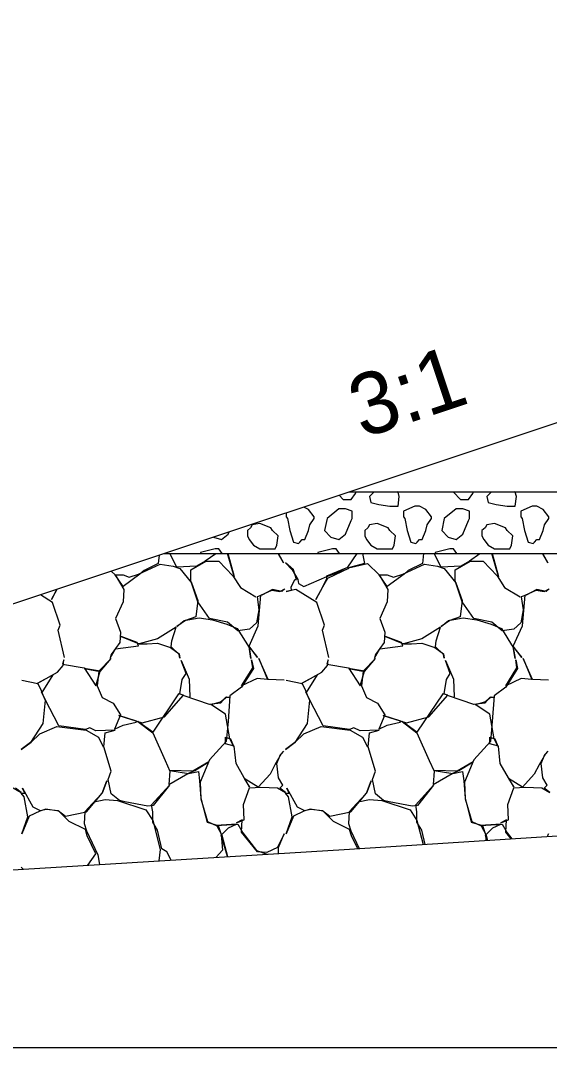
# Model space of a CAD drawing. Extents: x -26 to 4781, y -31 to 24738.
# Drawn here: x 2243.62 to 2252.18, y 8500 to 8516.63 of the extents above; entities that cross this region are included whole.
import ezdxf

# ---------------------------------------------------------------- set-up
doc = ezdxf.new("R2010")
doc.units = 0
for name, color, linetype in [('DESIGN - SHEET - Light Grid', 7, 'Continuous'), ('DESIGN - TRANSPORTATION - Proposed Layout Patterning', 7, 'Continuous'), ('DESIGN - TYPICAL - Finished Grade and Subgrade', 7, 'Continuous'), ('DESIGN - TYPICAL - Finished Grade Slopes Text', 7, 'Continuous'), ('GEOTECHNICAL – SCRATCH – Level 1', 7, 'Continuous'), ('SURVEY - GROUND - Top of Ground', 7, 'Continuous')]:
    doc.layers.add(name, color=color, linetype=linetype)

msp = doc.modelspace()

# ---------------------------------------------------------------- linework, layer by layer
at = {"layer": 'DESIGN - SHEET - Light Grid'}
msp.add_line((2000, 8500), (2300, 8500), dxfattribs=at)
at = {"layer": 'DESIGN - TRANSPORTATION - Proposed Layout Patterning'}
for p, q in [((2249.732, 8508.996), (2249.72, 8509)), ((2251.632, 8508.996), (2251.62, 8509)), ((2247.922, 8508.659), (2247.922, 8508.596)), ((2248.772, 8508.726), (2248.582, 8508.566)), ((2250.672, 8508.726), (2250.482, 8508.566)), ((2247.922, 8508.596), (2247.942, 8508.566)), ((2249.822, 8508.596), (2249.842, 8508.566)), ((2251.722, 8508.596), (2251.742, 8508.566))]:
    msp.add_line(p, q, dxfattribs=at)
for points in [[(2248.779, 8508.945), (2248.842, 8508.876), (2248.972, 8508.876), (2249.042, 8508.976), (2249.054, 8509)], [(2249.348, 8509), (2249.342, 8508.996), (2249.272, 8508.926), (2249.292, 8508.826), (2249.422, 8508.796), (2249.602, 8508.766), (2249.732, 8508.766), (2249.752, 8508.926), (2249.732, 8508.996)], [(2250.633, 8509), (2250.632, 8508.996), (2250.742, 8508.876), (2250.872, 8508.876), (2250.942, 8508.976), (2250.954, 8509)], [(2251.248, 8509), (2251.242, 8508.996), (2251.172, 8508.926), (2251.192, 8508.826), (2251.322, 8508.796), (2251.502, 8508.766), (2251.632, 8508.766), (2251.652, 8508.926), (2251.632, 8508.996)], [(2250.082, 8508.766), (2250.022, 8508.766), (2250.002, 8508.766), (2249.822, 8508.686), (2249.822, 8508.596)], [(2250.272, 8508.566), (2250.272, 8508.596), (2250.182, 8508.716), (2250.082, 8508.766)], [(2251.982, 8508.766), (2251.922, 8508.766), (2251.902, 8508.766), (2251.722, 8508.686), (2251.722, 8508.596)], [(2252.172, 8508.566), (2252.172, 8508.596), (2252.082, 8508.716), (2251.982, 8508.766)], [(2248.372, 8508.566), (2248.372, 8508.596), (2248.282, 8508.716), (2248.207, 8508.754)], [(2248.992, 8508.566), (2248.992, 8508.686), (2248.882, 8508.726), (2248.772, 8508.726)], [(2250.892, 8508.566), (2250.892, 8508.686), (2250.782, 8508.726), (2250.672, 8508.726)], [(2247.672, 8508.416), (2247.492, 8508.486), (2247.372, 8508.466), (2247.342, 8508.416), (2247.292, 8508.376), (2247.292, 8508.286), (2247.322, 8508.226), (2247.392, 8508.136), (2247.492, 8508.076), (2247.622, 8508.076), (2247.742, 8508.076), (2247.772, 8508.136), (2247.792, 8508.286), (2247.702, 8508.376), (2247.672, 8508.416)], [(2247.942, 8508.566), (2247.982, 8508.376), (2248.042, 8508.186), (2248.122, 8508.166), (2248.142, 8508.186), (2248.182, 8508.226)], [(2248.182, 8508.226), (2248.222, 8508.226), (2248.282, 8508.376), (2248.302, 8508.466), (2248.372, 8508.566)], [(2248.582, 8508.566), (2248.542, 8508.376), (2248.642, 8508.266), (2248.772, 8508.226), (2248.882, 8508.316), (2248.972, 8508.536), (2248.992, 8508.566)], [(2249.572, 8508.416), (2249.392, 8508.486), (2249.272, 8508.466), (2249.242, 8508.416), (2249.192, 8508.376), (2249.192, 8508.286), (2249.222, 8508.226), (2249.292, 8508.136), (2249.392, 8508.076), (2249.522, 8508.076), (2249.642, 8508.076), (2249.672, 8508.136), (2249.692, 8508.286), (2249.602, 8508.376), (2249.572, 8508.416)], [(2249.842, 8508.566), (2249.882, 8508.376), (2249.942, 8508.186), (2250.022, 8508.166), (2250.042, 8508.186), (2250.082, 8508.226)], [(2250.082, 8508.226), (2250.122, 8508.226), (2250.182, 8508.376), (2250.202, 8508.466), (2250.272, 8508.566)], [(2250.482, 8508.566), (2250.442, 8508.376), (2250.542, 8508.266), (2250.672, 8508.226), (2250.782, 8508.316), (2250.872, 8508.536), (2250.892, 8508.566)], [(2251.472, 8508.416), (2251.292, 8508.486), (2251.172, 8508.466), (2251.142, 8508.416), (2251.092, 8508.376), (2251.092, 8508.286), (2251.122, 8508.226), (2251.192, 8508.136), (2251.292, 8508.076), (2251.422, 8508.076), (2251.542, 8508.076), (2251.572, 8508.136), (2251.592, 8508.286), (2251.502, 8508.376), (2251.472, 8508.416)], [(2251.742, 8508.566), (2251.782, 8508.376), (2251.842, 8508.186), (2251.922, 8508.166), (2251.942, 8508.186), (2251.982, 8508.226)], [(2251.982, 8508.226), (2252.022, 8508.226), (2252.082, 8508.376), (2252.102, 8508.466), (2252.172, 8508.566)], [(2246.743, 8508.266), (2246.872, 8508.226), (2246.982, 8508.316), (2246.996, 8508.35)], [(2245.862, 8507.972), (2245.849, 8507.838), (2245.619, 8507.728), (2245.549, 8507.668), (2245.279, 8507.468), (2245.149, 8507.658), (2245.279, 8507.658), (2245.379, 8507.618), (2245.529, 8507.668), (2245.879, 8507.828), (2246.089, 8507.798), (2246.199, 8507.758), (2246.389, 8507.528), (2246.489, 8507.238), (2246.459, 8506.978), (2246.289, 8506.918), (2246.149, 8506.818), (2246.269, 8506.918), (2246.509, 8506.958), (2246.729, 8506.928), (2246.959, 8506.858), (2247.129, 8506.788), (2247.319, 8506.478), (2247.349, 8506.298), (2247.319, 8506.488), (2247.459, 8506.318), (2247.319, 8506.498), (2247.469, 8506.828), (2247.509, 8507.328), (2247.689, 8507.408), (2247.819, 8507.388), (2247.899, 8507.428), (2247.849, 8507.388), (2247.699, 8507.418), (2247.529, 8507.328), (2247.449, 8507.298), (2247.479, 8507.088), (2247.439, 8506.878), (2247.329, 8506.778), (2247.139, 8506.748), (2246.969, 8506.888), (2246.679, 8506.948), (2246.489, 8507.218), (2246.379, 8507.558), (2246.379, 8507.738), (2246.619, 8507.878), (2246.829, 8507.878), (2247.059, 8507.638), (2247.179, 8507.448), (2247.429, 8507.298)], [(2246.78, 8508), (2246.779, 8507.998), (2246.609, 8507.878), (2246.469, 8507.798), (2246.149, 8507.778), (2246.038, 8508)], [(2246.772, 8508.076), (2246.532, 8508.016), (2246.532, 8508)], [(2246.883, 8508), (2246.832, 8508.076), (2246.772, 8508.076)], [(2246.978, 8508), (2247.079, 8507.628), (2246.973, 8508)], [(2247.794, 8508), (2247.799, 8507.998), (2247.879, 8507.848), (2247.799, 8507.988), (2247.799, 8508)], [(2248.609, 8506.318), (2248.509, 8506.758), (2248.539, 8506.838), (2248.419, 8507.208), (2248.079, 8507.418), (2247.919, 8507.388), (2248.009, 8507.408), (2247.999, 8507.458), (2248.059, 8507.578), (2248.089, 8507.578), (2248.039, 8507.738), (2247.909, 8507.848), (2248.019, 8507.738), (2248.109, 8507.578), (2248.119, 8507.518), (2248.209, 8507.468), (2248.579, 8507.628), (2248.929, 8507.758), (2248.589, 8507.598), (2248.509, 8507.458), (2248.399, 8507.258), (2248.509, 8507.448), (2248.579, 8507.598), (2248.579, 8507.638), (2248.919, 8507.778), (2249.072, 8508)], [(2248.672, 8508.076), (2248.432, 8508.016), (2248.432, 8508)], [(2248.783, 8508), (2248.732, 8508.076), (2248.672, 8508.076)], [(2249.158, 8508), (2249.189, 8507.838), (2248.929, 8507.768), (2249.239, 8507.838), (2249.429, 8507.658), (2249.569, 8507.418), (2249.559, 8507.218), (2249.439, 8506.948), (2249.519, 8506.728), (2249.509, 8506.558), (2249.369, 8506.368), (2249.349, 8506.308), (2249.439, 8506.458), (2249.809, 8506.508), (2249.789, 8506.558), (2249.529, 8506.658), (2249.819, 8506.538), (2249.949, 8506.538), (2250.119, 8506.548), (2250.329, 8506.478), (2250.469, 8506.378), (2250.479, 8506.308), (2250.469, 8506.368), (2250.339, 8506.488), (2250.349, 8506.588), (2250.419, 8506.808), (2250.119, 8506.618), (2249.819, 8506.538)], [(2250.145, 8508), (2250.129, 8507.838), (2249.899, 8507.728), (2249.829, 8507.668), (2249.559, 8507.468), (2249.429, 8507.658), (2249.559, 8507.658), (2249.659, 8507.618), (2249.809, 8507.668), (2250.159, 8507.828), (2250.369, 8507.798), (2250.479, 8507.758), (2250.669, 8507.528), (2250.769, 8507.238), (2250.739, 8506.978), (2250.569, 8506.918), (2250.429, 8506.818), (2250.549, 8506.918), (2250.789, 8506.958), (2251.009, 8506.928), (2251.239, 8506.858), (2251.409, 8506.788), (2251.599, 8506.478), (2251.629, 8506.298), (2251.599, 8506.488), (2251.739, 8506.318), (2251.599, 8506.498), (2251.749, 8506.828), (2251.789, 8507.328), (2251.969, 8507.408), (2252.099, 8507.388), (2252.179, 8507.428), (2252.129, 8507.388), (2251.979, 8507.418), (2251.809, 8507.328), (2251.729, 8507.298), (2251.759, 8507.088), (2251.719, 8506.878), (2251.609, 8506.778), (2251.419, 8506.748), (2251.249, 8506.888), (2250.959, 8506.948), (2250.769, 8507.218), (2250.659, 8507.558), (2250.659, 8507.738), (2250.899, 8507.878), (2251.109, 8507.878), (2251.339, 8507.638), (2251.459, 8507.448), (2251.709, 8507.298)], [(2251.06, 8508), (2251.059, 8507.998), (2250.889, 8507.878), (2250.749, 8507.798), (2250.429, 8507.778), (2250.318, 8508)], [(2250.572, 8508.076), (2250.332, 8508.016), (2250.332, 8508)], [(2250.683, 8508), (2250.632, 8508.076), (2250.572, 8508.076)], [(2251.258, 8508), (2251.359, 8507.628), (2251.253, 8508)], [(2252.074, 8508), (2252.079, 8507.998), (2252.159, 8507.848), (2252.079, 8507.988), (2252.079, 8508)], [(2245.089, 8507.715), (2245.149, 8507.658), (2245.289, 8507.418), (2245.279, 8507.218), (2245.159, 8506.948), (2245.239, 8506.728), (2245.229, 8506.558), (2245.089, 8506.368), (2245.069, 8506.308), (2245.159, 8506.458), (2245.529, 8506.508), (2245.509, 8506.558), (2245.249, 8506.658), (2245.539, 8506.538), (2245.669, 8506.538), (2245.839, 8506.548), (2246.049, 8506.478), (2246.189, 8506.378), (2246.199, 8506.308), (2246.189, 8506.368), (2246.059, 8506.488), (2246.069, 8506.588), (2246.139, 8506.808), (2245.839, 8506.618), (2245.539, 8506.538)], [(2244.329, 8506.318), (2244.229, 8506.758), (2244.259, 8506.838), (2244.139, 8507.208), (2243.94, 8507.331)], [(2244.208, 8507.421), (2244.119, 8507.258), (2244.214, 8507.423)], [(2243.639, 8505.948), (2243.899, 8505.898), (2243.969, 8505.748), (2244.149, 8506.038), (2243.889, 8505.898), (2244.219, 8506.078), (2244.309, 8506.188), (2244.319, 8506.278), (2244.299, 8506.208), (2244.649, 8506.148), (2244.839, 8505.858), (2244.909, 8506.098), (2244.649, 8506.138), (2244.909, 8506.088), (2245.089, 8506.298), (2244.889, 8506.098), (2244.859, 8505.858), (2244.939, 8505.668), (2245.119, 8505.578), (2245.239, 8505.388), (2245.139, 8505.158), (2245.279, 8505.218), (2245.489, 8505.268), (2245.499, 8505.288), (2245.209, 8505.378), (2245.589, 8505.258), (2245.949, 8505.358), (2246.259, 8505.708), (2246.179, 8505.728), (2245.759, 8505.108), (2245.519, 8505.278), (2245.759, 8505.098), (2245.959, 8504.648), (2246.039, 8504.478), (2246.019, 8504.258), (2246.329, 8504.438), (2246.439, 8504.488), (2246.669, 8504.628), (2246.409, 8504.478), (2246.039, 8504.488), (2246.339, 8504.438), (2246.499, 8504.468), (2246.519, 8504.318), (2246.539, 8504.038), (2246.639, 8503.648), (2246.819, 8503.598), (2246.869, 8503.448), (2246.889, 8503.198), (2246.788, 8503.08)], [(2247.799, 8503.141), (2247.799, 8503.238), (2247.889, 8503.458), (2247.779, 8503.238), (2247.609, 8503.158), (2247.459, 8503.168), (2247.199, 8503.488), (2247.209, 8503.688), (2247.119, 8503.638), (2247.239, 8503.688), (2247.229, 8503.938), (2247.329, 8504.208), (2247.509, 8504.218), (2247.779, 8504.208), (2247.909, 8504.128), (2247.819, 8504.198), (2247.869, 8504.248), (2247.799, 8504.368), (2247.769, 8504.598), (2247.829, 8504.748), (2247.879, 8504.798), (2247.839, 8504.758), (2247.739, 8504.578), (2247.659, 8504.428), (2247.469, 8504.218), (2247.239, 8504.358), (2247.329, 8504.218), (2247.239, 8504.368), (2247.109, 8504.598), (2247.079, 8504.878), (2246.939, 8504.918), (2246.939, 8505.028), (2247.019, 8504.998), (2247.069, 8504.878), (2247.009, 8504.998), (2246.939, 8505.398), (2246.699, 8505.558), (2246.859, 8505.598), (2246.959, 8505.678), (2247.009, 8505.668), (2246.939, 8505.668), (2246.859, 8505.578), (2246.679, 8505.558), (2246.269, 8505.698), (2246.199, 8505.728), (2246.239, 8505.958), (2246.299, 8506.058), (2246.219, 8506.268), (2246.349, 8505.968), (2246.359, 8505.678)], [(2247.889, 8505.948), (2247.629, 8505.958), (2247.479, 8506.298), (2247.619, 8505.958), (2247.449, 8505.978), (2247.199, 8505.858), (2247.379, 8506.148), (2247.359, 8506.278), (2247.389, 8506.138), (2247.199, 8505.838), (2247.009, 8505.698), (2246.979, 8505.278), (2246.949, 8504.958), (2246.679, 8504.658), (2246.529, 8504.298), (2246.539, 8504.028), (2246.649, 8503.658), (2246.799, 8503.588), (2246.879, 8503.438), (2246.973, 8503.091)], [(2247.919, 8505.948), (2248.179, 8505.898), (2248.249, 8505.748), (2248.429, 8506.038), (2248.169, 8505.898), (2248.499, 8506.078), (2248.589, 8506.188), (2248.599, 8506.278), (2248.579, 8506.208), (2248.929, 8506.148), (2249.119, 8505.858), (2249.189, 8506.098), (2248.929, 8506.138), (2249.189, 8506.088), (2249.369, 8506.298), (2249.169, 8506.098), (2249.139, 8505.858), (2249.219, 8505.668), (2249.399, 8505.578), (2249.519, 8505.388), (2249.419, 8505.158), (2249.559, 8505.218), (2249.769, 8505.268), (2249.779, 8505.288), (2249.489, 8505.378), (2249.869, 8505.258), (2250.229, 8505.358), (2250.539, 8505.708), (2250.459, 8505.728), (2250.039, 8505.108), (2249.799, 8505.278), (2250.039, 8505.098), (2250.239, 8504.648), (2250.319, 8504.478), (2250.299, 8504.258), (2250.609, 8504.438), (2250.719, 8504.488), (2250.949, 8504.628), (2250.689, 8504.478), (2250.319, 8504.488), (2250.619, 8504.438), (2250.779, 8504.468), (2250.799, 8504.318), (2250.819, 8504.038), (2250.919, 8503.648), (2251.099, 8503.598), (2251.149, 8503.448), (2251.156, 8503.354)], [(2251.567, 8503.38), (2251.479, 8503.488), (2251.489, 8503.688), (2251.399, 8503.638), (2251.519, 8503.688), (2251.509, 8503.938), (2251.609, 8504.208), (2251.789, 8504.218), (2252.059, 8504.208), (2252.189, 8504.128), (2252.099, 8504.198), (2252.149, 8504.248), (2252.079, 8504.368), (2252.049, 8504.598), (2252.109, 8504.748), (2252.159, 8504.798), (2252.119, 8504.758), (2252.019, 8504.578), (2251.939, 8504.428), (2251.749, 8504.218), (2251.519, 8504.358), (2251.609, 8504.218), (2251.519, 8504.368), (2251.389, 8504.598), (2251.359, 8504.878), (2251.219, 8504.918), (2251.219, 8505.028), (2251.299, 8504.998), (2251.349, 8504.878), (2251.289, 8504.998), (2251.219, 8505.398), (2250.979, 8505.558), (2251.139, 8505.598), (2251.239, 8505.678), (2251.289, 8505.668), (2251.219, 8505.668), (2251.139, 8505.578), (2250.959, 8505.558), (2250.549, 8505.698), (2250.479, 8505.728), (2250.519, 8505.958), (2250.579, 8506.058), (2250.499, 8506.268), (2250.629, 8505.968), (2250.639, 8505.678)], [(2252.169, 8505.948), (2251.909, 8505.958), (2251.759, 8506.298), (2251.899, 8505.958), (2251.729, 8505.978), (2251.479, 8505.858), (2251.659, 8506.148), (2251.639, 8506.278), (2251.669, 8506.138), (2251.479, 8505.838), (2251.289, 8505.698), (2251.259, 8505.278), (2251.229, 8504.958), (2250.959, 8504.658), (2250.809, 8504.298), (2250.819, 8504.028), (2250.929, 8503.658), (2251.079, 8503.588), (2251.159, 8503.438), (2251.181, 8503.355)], [(2246.056, 8503.035), (2245.989, 8503.168), (2245.909, 8503.218), (2245.839, 8503.518), (2245.759, 8503.648), (2245.759, 8503.818), (2245.739, 8503.928), (2246.029, 8504.248), (2245.769, 8503.918), (2245.679, 8503.908), (2245.309, 8503.978), (2245.219, 8503.998), (2245.089, 8504.108), (2245.039, 8504.338), (2245.089, 8504.478), (2244.969, 8504.868), (2244.989, 8505.098), (2245.149, 8505.138), (2244.839, 8505.128), (2244.739, 8505.178), (2244.669, 8505.148), (2244.239, 8505.208), (2244.019, 8505.638), (2243.959, 8505.758), (2244.019, 8505.628), (2243.979, 8505.248), (2243.779, 8504.938), (2243.629, 8504.828), (2243.789, 8504.948), (2243.929, 8505.078), (2244.209, 8505.198), (2244.679, 8505.138), (2244.879, 8505.028), (2244.959, 8504.868)], [(2250.172, 8503.29), (2250.119, 8503.518), (2250.039, 8503.648), (2250.039, 8503.818), (2250.019, 8503.928), (2250.309, 8504.248), (2250.049, 8503.918), (2249.959, 8503.908), (2249.589, 8503.978), (2249.499, 8503.998), (2249.369, 8504.108), (2249.319, 8504.338), (2249.369, 8504.478), (2249.249, 8504.868), (2249.269, 8505.098), (2249.429, 8505.138), (2249.119, 8505.128), (2249.019, 8505.178), (2248.949, 8505.148), (2248.519, 8505.208), (2248.299, 8505.638), (2248.239, 8505.758), (2248.299, 8505.628), (2248.259, 8505.248), (2248.059, 8504.938), (2247.909, 8504.828), (2248.069, 8504.948), (2248.209, 8505.078), (2248.489, 8505.198), (2248.959, 8505.138), (2249.159, 8505.028), (2249.239, 8504.868)], [(2244.711, 8502.952), (2244.839, 8503.138), (2244.699, 8503.428), (2244.669, 8503.528), (2244.409, 8503.658), (2244.329, 8503.738), (2244.239, 8503.828), (2244.029, 8503.858), (2243.929, 8503.828), (2243.759, 8503.748), (2243.639, 8503.458), (2243.739, 8503.738), (2243.679, 8504.058), (2243.629, 8504.118), (2243.689, 8504.118), (2243.649, 8504.198), (2243.819, 8503.898), (2243.939, 8503.838), (2244.039, 8503.858), (2244.229, 8503.838), (2244.349, 8503.748), (2244.689, 8503.818), (2244.939, 8504.118), (2245.019, 8504.318), (2244.939, 8504.118), (2244.779, 8503.948), (2244.659, 8503.818), (2244.649, 8503.628), (2244.689, 8503.508), (2244.869, 8503.118), (2244.898, 8502.964)], [(2249.079, 8503.22), (2248.979, 8503.428), (2248.949, 8503.528), (2248.689, 8503.658), (2248.609, 8503.738), (2248.519, 8503.828), (2248.309, 8503.858), (2248.209, 8503.828), (2248.039, 8503.748), (2247.919, 8503.458), (2248.019, 8503.738), (2247.959, 8504.058), (2247.909, 8504.118), (2247.969, 8504.118), (2247.929, 8504.198), (2248.099, 8503.898), (2248.219, 8503.838), (2248.319, 8503.858), (2248.509, 8503.838), (2248.629, 8503.748), (2248.969, 8503.818), (2249.219, 8504.118), (2249.299, 8504.318), (2249.219, 8504.118), (2249.059, 8503.948), (2248.939, 8503.818), (2248.929, 8503.628), (2248.969, 8503.508), (2249.101, 8503.222)], [(2243.499, 8504.208), (2243.629, 8504.128), (2243.539, 8504.198)], [(2244.809, 8503.978), (2244.989, 8504.018), (2245.189, 8503.998), (2245.649, 8503.848), (2245.759, 8503.678), (2245.879, 8503.208), (2245.86, 8503.023)], [(2249.089, 8503.978), (2249.269, 8504.018), (2249.469, 8503.998), (2249.929, 8503.848), (2250.039, 8503.678), (2250.138, 8503.288)], [(2246.968, 8503.091), (2246.869, 8503.438), (2246.989, 8503.558), (2247.119, 8503.618), (2246.789, 8503.598), (2247.139, 8503.618), (2247.219, 8503.478), (2247.439, 8503.188), (2247.613, 8503.13)], [(2251.173, 8503.355), (2251.149, 8503.438), (2251.269, 8503.558), (2251.399, 8503.618), (2251.069, 8503.598), (2251.419, 8503.618), (2251.499, 8503.478), (2251.573, 8503.38)], [(2252.152, 8503.417), (2252.169, 8503.458), (2252.148, 8503.417)], [(2243.664, 8502.888), (2243.629, 8502.918), (2243.659, 8502.888)]]:
    msp.add_lwpolyline(points, dxfattribs=at)
at = {"layer": 'DESIGN - TYPICAL - Finished Grade and Subgrade'}
msp.add_line((2271.849, 8516.635), (2229.413, 8502.489), dxfattribs=at)
at = {"layer": 'GEOTECHNICAL – SCRATCH – Level 1'}
for p, q in [((2248.946, 8509), (2318.356, 8509)), ((2245.946, 8508), (2312.107, 8508))]:
    msp.add_line(p, q, dxfattribs=at)
at = {"layer": 'SURVEY - GROUND - Top of Ground'}
msp.add_lwpolyline([(2242.783, 8502.834), (2248.858, 8503.206), (2253.993, 8503.535), (2257.472, 8503.675), (2261.959, 8503.957), (2266.455, 8504.253), (2270.459, 8504.568), (2273.125, 8504.748), (2279.12, 8505.167), (2290.167, 8505.937), (2290.7, 8505.972), (2297.309, 8506.468), (2300, 8506.682), (2303.408, 8506.952), (2307.215, 8507.358), (2314.513, 8508.315), (2321.735, 8509.602)], dxfattribs=at)

# ---------------------------------------------------------------- texts
at = {"layer": 'DESIGN - TYPICAL - Finished Grade Slopes Text'}
msp.add_text('3:1', height=1, rotation=18.4349, dxfattribs=at).set_placement((2249.154, 8509.86))

doc.saveas('drawing.dxf')
